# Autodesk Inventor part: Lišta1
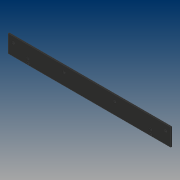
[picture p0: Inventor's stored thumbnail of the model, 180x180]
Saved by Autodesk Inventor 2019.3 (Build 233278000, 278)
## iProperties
Created: 2019-02
Part Number: Lišta1
Material: PVC, nepoplastované
Document SubType Name: Modeling
Designer: B-hon
Density: 1.29 g/cm^3
Appearance: Guma – černá
Author: B-hon
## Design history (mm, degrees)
sketch "Náčrt1"
  geometry: L1 (352, -38)-(-352, -38); L2 (-352, -38)-(-352, 38); L3 (-352, 38)-(352, 38); L4 (352, 38)-(352, -38); L5 (352, -38)-(-352, 38); L6 (-352, -38)-(352, 38); 1 further point
  constraints: 12 end point, 2 midpoint, 2 parallel, 1 horizontal, 1 perpendicular
  dimensions: "d0" = 704 distance of L2.end L3.end; "d1" = 76 distance of L1.end L2.end
extrude "Vysunutí1" new body sketch "Náčrt1" distance "d2" = 5; taper "d3" = 0 deg
sketch "Náčrt2"
  geometry: L1 (-352, 38)-(-352, -38) reference; L2 (352, 38)-(-352, 38) reference; 2 further points
  dimensions: "d4" = 22 distance from line of L1 point (-330, 13); "d5" = 25 distance from line of point (-330, 13) L2
hole "Díra1" sketch "Náčrt2" at (-330, 13) diameter "d6" = 5.5; stored, may be unused: countersink angle "d10" = 90 deg, drill point angle "d12" = 0 deg; dims "d7" = 6, "d8" = 9.5, "d9" = 2, "d11" = 8
pattern_linear "Obdélníkové pole1" dims "d15" = 220
sketch "Náčrt3"
  geometry: L1 (-352, -38)-(352, -38) reference; L2 (-352, 38)-(-352, -38) reference; L3 (352, -38)-(352, 38) reference; 5 further points
  constraints: 2 horizontal alignment, 2 vertical alignment
  dimensions: "d16" = 7 distance from line of L1 point (-266, -31); "d17" = 86 distance from line of L2 point (-266, -13); "d18" = 86 distance from line of L3 point (266, -31); "d19" = 18 distance of point (-266, -13) point (-266, -31)
hole "Díra2" sketch "Náčrt3" at (-266, -31), (-266, -13), (266, -31), (266, -13) diameter "d20" = 5.5; stored, may be unused: countersink angle "d24" = 90 deg, drill point angle "d26" = 0 deg; dims "d21" = 6, "d22" = 9.5, "d23" = 2, "d25" = 8
node "Těleso1"
